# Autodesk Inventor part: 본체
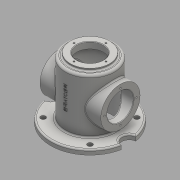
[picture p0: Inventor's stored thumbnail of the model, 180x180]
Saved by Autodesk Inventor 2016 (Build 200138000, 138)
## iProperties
Created: 2018-04
Part Number: 본체
Material: 일반
Document SubType Name: Modeling
Designer: 605-15
Density: 1 g/cm^3
Appearance: 기본값
Author: 605-15
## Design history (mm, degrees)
sketch "스케치1"
  geometry: C1 r 50 at (0, 0); 1 further point
  constraints: 1 centre point, 1 coincident
  dimensions: "d0" = 100 diameter of C1
extrude "돌출1" new body sketch "스케치1" distance "d1" = 8; taper "d2" = 0 deg
sketch "스케치2"
  geometry: C1 r 80 at (0, 0); 1 further point
  constraints: 1 centre point, 1 coincident
  dimensions: "d3" = 160 diameter of C1
extrude "돌출2" join sketch "스케치2" distance "d4" = 10; taper "d5" = 0 deg
sketch "스케치3"
  geometry: C1 r 50 at (0, 0); 1 further point
  constraints: 1 centre point, 1 coincident
  dimensions: "d6" = 100 diameter of C1
extrude "돌출3" join sketch "스케치3" distance "d7" = 110; taper "d8" = 0 deg
sketch "스케치4"
  geometry: C1 r 40 at (0, 0); 1 further point
  constraints: 1 centre point, 1 coincident
  dimensions: "d9" = 80 diameter of C1
extrude "돌출4" join sketch "스케치4" distance "d10" = 5; taper "d11" = 0 deg
sketch "스케치7"
  geometry: L1 (-80, 8)-(80, 8) reference; L2 (50, 8)-(-50, 8) reference; L3 (0, 8)-(0, 68); C1 r 40 at (0, 68); 1 further point
  constraints: 2 end point, 1 centre point, 1 coincident, 1 midpoint, 1 vertical
  dimensions: "d18" = 60 distance of L3.start L3.end; "d19" = 80 diameter of C1
extrude "돌출7" join sketch "스케치7" stored distance "d20" = 124; taper "d21" = 0 deg
sketch "스케치8"
  geometry: C1 r 27 at (0, 0); 1 further point
  constraints: 1 centre point
  dimensions: "d22" = 54 diameter of C1
extrude "돌출8" cut sketch "스케치8" stored distance "d23" = 124; taper "d24" = 0 deg
sketch "스케치9"
  geometry: C1 r 45 at (0, 0); 1 further point
  constraints: 1 centre point, 1 coincident
  dimensions: "d25" = 90 diameter of C1
extrude "돌출9" cut sketch "스케치9" distance "d26" = 120; taper "d27" = 0 deg
sketch "스케치10"
  geometry: C1 r 27 at (0, 0); 1 further point
  constraints: 1 centre point, 1 coincident
  dimensions: "d28" = 54 diameter of C1
extrude "돌출10" cut sketch "스케치10" distance "d29" = 13; taper "d30" = 0 deg
sketch "스케치11"
  geometry: A1 r 32.5 centre (0, 0) between (0, 32.5) and (32.5, 0); 3 further points
  constraints: 4 point on circle, 1 centre point, 1 coincident
  dimensions: "d31" = 65 diameter of A1
hole "구멍1" sketch "스케치11" at (0, 32.5), (32.5, 0), (0, -32.5), (-32.5, 0) diameter "d32" = 3.242; stored, may be unused: countersink angle "d36" = 90 deg, drill point angle "d38" = 118 deg; dims "d33" = 8, "d34" = 4, "d35" = 2, "d37" = 10
sketch "스케치12"
  geometry: A1 r 32.5 centre (0, 0) between (32.5, 0) and (0, -32.5); 3 further points
  constraints: 4 point on circle, 1 centre point
  dimensions: "d39" = 65 diameter of A1
hole "구멍2" sketch "스케치12" at (32.5, 0), (0, -32.5), (-32.5, 0), (0, 32.5) diameter "d40" = 3.242; stored, may be unused: countersink angle "d44" = 90 deg, drill point angle "d46" = 118 deg; dims "d41" = 8, "d42" = 4, "d43" = 2, "d45" = 10
sketch "스케치13"
  geometry: C1 r 15 at (-80, 0); C2 r 15 at (80, 0); A1 r 80 centre (0, 0) between (-80, 0) and (80, 0) reference; 1 further point
  constraints: 2 centre point, 2 point on circle
  dimensions: "d49" = 30 diameter of C1; "d50" = 30 diameter of C2
extrude "돌출11" cut sketch "스케치13" stored distance "d51" = 13; taper "d52" = 0 deg
sketch "스케치14"
  geometry: L1 (0, 0)-(0, 80); L2 (0, 0)-(74.498, 74.498); L3 (0, 0)-(0, -80); L4 (0, 0)-(98.351, -98.351); C1 r 5 at (47.73, 47.73); C2 r 5 at (47.73, -47.73); A1 r 80 centre (0, 0) between (78.594, 14.934) and (-78.594, 14.934) reference; A2 r 67.5 centre (0, 0) between (47.73, 47.73) and (47.73, -47.73)
  constraints: 8 end point, 3 centre point, 3 point on circle, 2 point on line, 2 vertical, 1 coincident
  dimensions: "d53" = 45 deg angle of L1 L2; "d54" = 45 deg angle of L4 L3; "d55" = 135 diameter of A2; "d56" = 10 diameter of C1; "d57" = 10 diameter of C2
extrude "돌출12" cut sketch "스케치14" stored distance "d58" = 13; taper "d59" = 0 deg
node "작업 평면1"
node "작업 평면2"
sketch "스케치15"
  geometry: L1 (-6.424, 52.038)-(-6.424, 103.962); L2 (-6.424, 103.962)-(6.424, 103.962); L3 (6.424, 103.962)-(6.424, 52.038); L4 (6.424, 52.038)-(-6.424, 52.038); L5 (0, 103.962)-(0, 52.038); L6 (6.424, 78)-(-6.424, 78); L7 (50, 8)-(-50, 8) reference; L8 (0, 8)-(0, 78); 2 further points
  constraints: 6 end point, 6 midpoint, 1 vertical, 2 other
  dimensions: "d74" = 70 distance of L8.start L8.end
feature "엠보싱1" sketch "스케치15" dims "d2" = 0, "d62" = 0.5, "d63" = 0
fillet "모깎기1" dims "d64" = 3
fillet "모깎기3" dims "d66" = 3
chamfer "모따기1" distance "d67" = 1; stored, may be unused: second distance "d68" = 2, angle "d69" = 45 deg
fillet "모깎기4" dims "d70" = 3
fillet "모깎기5" dims "d71" = 3, "d72" = 5
chamfer "모따기2" distance "d75" = 1; stored, may be unused: second distance "d76" = 2, angle "d77" = 45 deg
node "솔리드1"
mirror "대칭1"
mirror "대칭2"
other parameters: "d60" = -147.25
